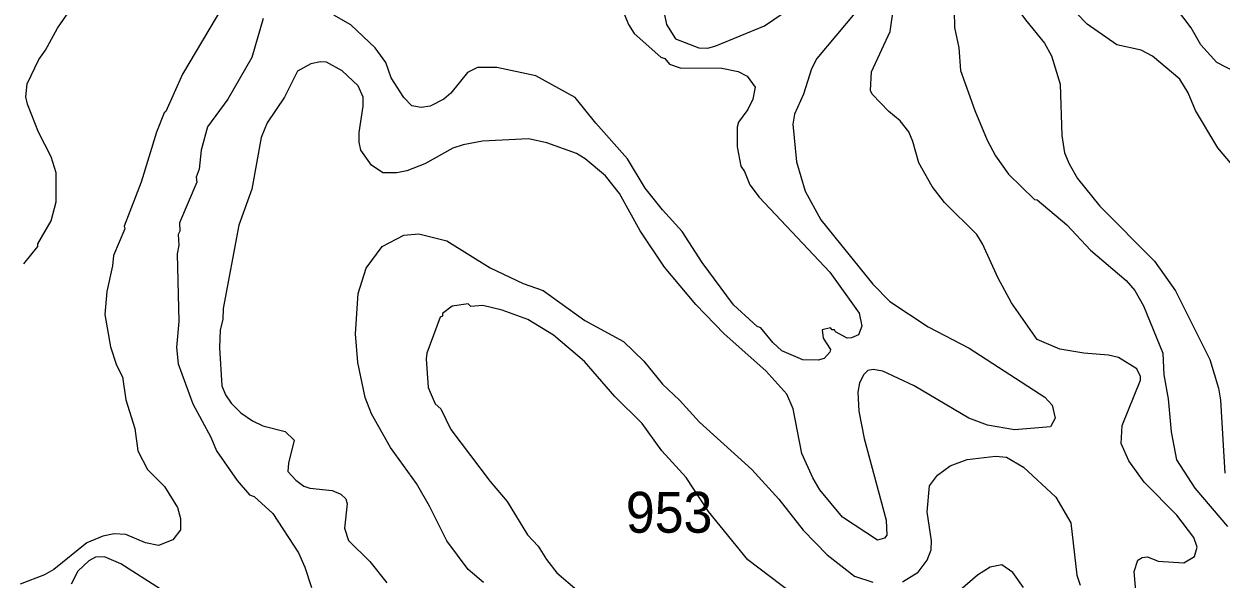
# Model space of a CAD drawing. Extents: x 447.8 to 473.9, y 7733.1 to 7760.8.
# Drawn here: x 451.054 to 453.399, y 7747.855 to 7748.942 of the extents above; entities that cross this region are included whole.
import ezdxf

# ---------------------------------------------------------------- set-up
doc = ezdxf.new("R2010")
doc.units = 0
doc.header["$LTSCALE"] = 0.032
doc.layers.add('1', color=7, linetype='Continuous', lineweight=25)
doc.layers.add('2', color=7, linetype='Continuous', lineweight=13)
doc.layers.add('21', color=7, linetype='Continuous')

msp = doc.modelspace()

# ---------------------------------------------------------------- linework, layer by layer
at = {"layer": '1'}
for points in [[(452.3083, 7748.9635), (452.3123, 7748.941), (452.3305, 7748.9134), (452.3757, 7748.8958), (452.3933, 7748.895), (452.4095, 7748.8993), (452.5046, 7748.9386), (452.5775, 7748.9883)], [(452.6817, 7748.9633), (452.6069, 7748.8749), (452.5964, 7748.8544), (452.5806, 7748.8048), (452.5632, 7748.7655), (452.56, 7748.7464), (452.5673, 7748.6725), (452.5842, 7748.6148), (452.6151, 7748.5585), (452.7169, 7748.4327), (452.7503, 7748.3985), (452.825, 7748.3492), (452.9055, 7748.3077), (453.0538, 7748.2111), (453.0681, 7748.1958), (453.0738, 7748.1705), (453.0648, 7748.1536), (452.9942, 7748.1471), (452.9413, 7748.1567), (452.905, 7748.1701), (452.7978, 7748.2338), (452.736, 7748.2625), (452.7172, 7748.2656), (452.7068, 7748.2639), (452.6988, 7748.256), (452.6906, 7748.2397), (452.6875, 7748.2212), (452.689, 7748.1843), (452.6997, 7748.1303), (452.7427, 7747.9707), (452.7442, 7747.9408), (452.7393, 7747.935), (452.7261, 7747.9311), (452.6574, 7747.9761), (452.6132, 7748.0297), (452.5989, 7748.0531), (452.5774, 7748.1013), (452.5609, 7748.1884), (452.5481, 7748.217), (452.5072, 7748.2631), (452.4253, 7748.3354), (452.3698, 7748.3926), (452.3089, 7748.4663), (452.2608, 7748.5369), (452.2208, 7748.6101), (452.193, 7748.6447), (452.1535, 7748.6779), (452.136, 7748.6889), (452.0782, 7748.7095), (452.0426, 7748.7177), (451.9524, 7748.7129), (451.9143, 7748.7058), (451.8944, 7748.6992), (451.8395, 7748.6685), (451.8041, 7748.6547), (451.7845, 7748.6505), (451.7572, 7748.6505), (451.7346, 7748.6656), (451.714, 7748.6951), (451.7104, 7748.711), (451.7104, 7748.7298), (451.7183, 7748.7816), (451.7183, 7748.7992), (451.7087, 7748.8214), (451.6776, 7748.8505), (451.6469, 7748.8673), (451.6346, 7748.8684), (451.6158, 7748.8644), (451.5902, 7748.8499), (451.5647, 7748.7988)], [(451.5647, 7748.7988), (451.5307, 7748.7487), (451.5186, 7748.7198), (451.5004, 7748.6187), (451.4747, 7748.5482), (451.4446, 7748.3853)], [(451.4446, 7748.3853), (451.4434, 7748.3634), (451.4386, 7748.3434), (451.4371, 7748.3083), (451.4419, 7748.2336), (451.4489, 7748.2163), (451.4601, 7748.1996), (451.479, 7748.1804), (451.5019, 7748.165), (451.522, 7748.1554), (451.5657, 7748.1439), (451.5834, 7748.127), (451.5721, 7748.0821), (451.5709, 7748.0656), (451.5867, 7748.0487), (451.6022, 7748.0373), (451.6142, 7748.0334), (451.6578, 7748.0283), (451.675, 7748.0211), (451.6846, 7748.0121), (451.687, 7748.0023), (451.6816, 7747.9551), (451.6896, 7747.9307), (451.7314, 7747.8895), (451.7651, 7747.848)]]:
    msp.add_lwpolyline(points, dxfattribs=at)
at = {"layer": '2'}
for points in [[(453.4872, 7748.5874), (453.3925, 7748.6995), (453.3485, 7748.7728), (453.3342, 7748.8078), (453.3181, 7748.8342), (453.2643, 7748.8795), (453.2423, 7748.8911), (453.1947, 7748.9015), (453.1364, 7748.9418), (453.1153, 7748.9633), (453.0416, 7749.0649), (452.9876, 7749.1081), (452.9487, 7749.1264), (452.9395, 7749.1254), (452.9296, 7749.1185), (452.9208, 7749.1038), (452.9208, 7749.0866), (452.9245, 7749.0742), (453.0157, 7748.9502), (453.0527, 7748.9048), (453.0665, 7748.88)], [(451.4433, 7748.9757), (451.3646, 7748.8439), (451.3321, 7748.7709), (451.3285, 7748.7682), (451.3135, 7748.7303), (451.2838, 7748.6326), (451.2504, 7748.5462), (451.2516, 7748.5412), (451.2296, 7748.4892), (451.2277, 7748.4689), (451.2163, 7748.4184), (451.2126, 7748.3736), (451.2238, 7748.3099), (451.2357, 7748.274), (451.247, 7748.2512), (451.2535, 7748.206), (451.2711, 7748.1502), (451.2773, 7748.106), (451.2963, 7748.0696), (451.3294, 7748.0367), (451.3548, 7747.9952), (451.3608, 7747.9739), (451.3608, 7747.9518), (451.3459, 7747.9317), (451.3177, 7747.9211), (451.2919, 7747.9258), (451.2534, 7747.9426), (451.231, 7747.9434), (451.2085, 7747.9394), (451.1776, 7747.9263), (451.1129, 7747.8741), (451.0944, 7747.8631), (451.0469, 7747.8449)], [(451.054, 7748.4728), (451.0816, 7748.5067), (451.0813, 7748.5118), (451.1073, 7748.557), (451.1171, 7748.5943), (451.117, 7748.6511), (451.1074, 7748.682), (451.0829, 7748.7304), (451.061, 7748.7854), (451.0578, 7748.7996), (451.0602, 7748.8248), (451.0834, 7748.873), (451.0964, 7748.8912), (451.12, 7748.9344), (451.1479, 7748.9748)], [(452.2189, 7748.9878), (452.2383, 7748.9412), (452.2491, 7748.9236), (452.3015, 7748.8773), (452.309, 7748.8747), (452.3185, 7748.8637), (452.3394, 7748.8565), (452.4208, 7748.8556), (452.4529, 7748.8491), (452.4704, 7748.84), (452.4862, 7748.8184), (452.4815, 7748.795), (452.4719, 7748.7747), (452.4535, 7748.7498), (452.4511, 7748.7405), (452.4511, 7748.7015), (452.458, 7748.6639), (452.4654, 7748.6536), (452.4758, 7748.6276), (452.494, 7748.6034), (452.6323, 7748.4562), (452.6897, 7748.3759), (452.6954, 7748.3506), (452.6884, 7748.3335), (452.6751, 7748.3274), (452.6665, 7748.3269), (452.6437, 7748.3395), (452.6419, 7748.3431), (452.6369, 7748.343), (452.6336, 7748.3473), (452.6174, 7748.3436), (452.6193, 7748.3269), (452.6336, 7748.3049), (452.6326, 7748.2997), (452.6214, 7748.287), (452.6097, 7748.2842), (452.5796, 7748.2846), (452.5383, 7748.3024), (452.5211, 7748.3182), (452.4975, 7748.3473), (452.4899, 7748.35), (452.4441, 7748.3921), (452.3824, 7748.4752), (452.3434, 7748.5361), (452.3046, 7748.5781), (452.271, 7748.621), (452.2359, 7748.678), (452.174, 7748.7479), (452.1338, 7748.7983), (452.0569, 7748.8411), (451.98, 7748.8572), (451.9424, 7748.8572), (451.9228, 7748.8476), (451.8901, 7748.8067), (451.8766, 7748.7952), (451.8495, 7748.7812), (451.8319, 7748.7787), (451.814, 7748.7817), (451.7981, 7748.7985), (451.7734, 7748.8371), (451.763, 7748.8671), (451.7422, 7748.8954), (451.6946, 7748.9404), (451.6613, 7748.9596)], [(453.2325, 7747.824), (453.2286, 7747.87), (453.2358, 7747.8924), (453.2444, 7747.8974), (453.2549, 7747.8984), (453.2758, 7747.8904), (453.3257, 7747.8868), (453.3468, 7747.8995), (453.3517, 7747.9179), (453.3453, 7747.9365), (453.3119, 7747.9802), (453.2481, 7748.0446), (453.2179, 7748.0867), (453.2033, 7748.1204), (453.2049, 7748.156), (453.2412, 7748.245), (453.2409, 7748.2519), (453.2335, 7748.2666), (453.1976, 7748.2889), (453.1781, 7748.2937), (453.1299, 7748.2978), (453.0827, 7748.3057), (453.0388, 7748.3243), (452.9881, 7748.3959), (452.9619, 7748.4446), (452.9314, 7748.5116), (452.9201, 7748.5297), (452.857, 7748.5927), (452.8326, 7748.624), (452.8065, 7748.6702), (452.7953, 7748.7123), (452.7869, 7748.7314), (452.7699, 7748.7529), (452.7479, 7748.771), (452.7157, 7748.805), (452.7124, 7748.8122), (452.7139, 7748.8487), (452.7506, 7748.9274), (452.7587, 7748.9816)], [(453.5469, 7748.7861), (453.3904, 7748.8669), (453.3588, 7748.9016), (453.3399, 7748.935), (453.2971, 7748.9922)], [(451.5225, 7748.9528), (451.5003, 7748.8765), (451.4534, 7748.7954), (451.4134, 7748.7407), (451.4014, 7748.6949), (451.3976, 7748.6577), (451.3914, 7748.642), (451.3929, 7748.6328), (451.3586, 7748.5529), (451.3592, 7748.5364), (451.3561, 7748.53), (451.3576, 7748.5093), (451.3545, 7748.4924), (451.3577, 7748.3596), (451.3528, 7748.3085)], [(452.8758, 7748.9678), (452.8767, 7748.9352), (452.8854, 7748.8957), (452.8887, 7748.8512), (452.9162, 7748.7732), (452.9405, 7748.715), (452.957, 7748.6842), (452.9824, 7748.6479), (453.0335, 7748.5987), (453.0387, 7748.5979), (453.0969, 7748.5487), (453.1433, 7748.4992), (453.2127, 7748.4402), (453.2297, 7748.4201), (453.2465, 7748.3901), (453.2846, 7748.2977), (453.2863, 7748.2554), (453.295, 7748.2079), (453.3008, 7748.1438), (453.3116, 7748.0887), (453.3472, 7748.0332), (453.4114, 7747.9584)], [(453.0665, 7748.88), (453.0833, 7748.8242), (453.0867, 7748.7238), (453.0923, 7748.6902), (453.101, 7748.6683), (453.1175, 7748.6398)], [(453.1175, 7748.6398), (453.1613, 7748.5855), (453.2686, 7748.4781), (453.3095, 7748.4195), (453.3767, 7748.2852), (453.3936, 7748.2288), (453.3977, 7748.2056), (453.4062, 7748.0623)], [(451.9542, 7747.8482), (451.9239, 7747.8741), (451.8821, 7747.9303), (451.8487, 7747.9982), (451.8228, 7748.0422), (451.7719, 7748.1131), (451.7346, 7748.1787), (451.7222, 7748.2106), (451.708, 7748.2793), (451.7032, 7748.3355), (451.7087, 7748.4146), (451.7246, 7748.4639), (451.7554, 7748.5067), (451.7984, 7748.5284), (451.8274, 7748.5316), (451.8821, 7748.5179), (451.967, 7748.465), (452.0321, 7748.4342), (452.0709, 7748.4202), (452.1529, 7748.3614), (452.2283, 7748.3206), (452.2685, 7748.282), (452.3048, 7748.2371), (452.3378, 7748.2056), (452.3772, 7748.1622)], [(452.5797, 7747.8113), (452.4721, 7747.8927), (452.395, 7747.9875), (452.3512, 7748.0538), (452.3035, 7748.1063), (452.2648, 7748.1601), (452.2113, 7748.2128), (452.1518, 7748.2812), (452.0913, 7748.3327), (452.0409, 7748.3633), (451.9905, 7748.3816), (451.9527, 7748.3912), (451.9296, 7748.3892), (451.9239, 7748.3939), (451.8925, 7748.3898), (451.8741, 7748.3754), (451.8736, 7748.3699), (451.8693, 7748.3681), (451.8434, 7748.2973), (451.8419, 7748.2862), (451.8459, 7748.2301)], [(451.3528, 7748.3085), (451.3561, 7748.2766), (451.3851, 7748.1981), (451.42, 7748.1329), (451.4311, 7748.1062), (451.4714, 7748.0482)], [(451.8459, 7748.2301), (451.8596, 7748.1985), (451.8706, 7748.1887), (451.8901, 7748.1484), (451.9673, 7748.046), (452.0007, 7748.0073)], [(452.3772, 7748.1622), (452.4794, 7748.0695), (452.5326, 7748.0114), (452.5802, 7747.9511), (452.6273, 7747.9024), (452.6807, 7747.8605)], [(452.7751, 7747.85), (452.8056, 7747.8688), (452.8228, 7747.8921), (452.8309, 7747.9123), (452.8316, 7747.9298), (452.823, 7747.9867), (452.8279, 7748.0379), (452.8434, 7748.0584), (452.868, 7748.0771), (452.9015, 7748.0892), (452.9571, 7748.0956), (452.9785, 7748.0937), (453.0119, 7748.0744), (453.0751, 7748.0157), (453.1048, 7747.9653), (453.1163, 7747.863), (453.1227, 7747.8435)], [(451.4714, 7748.0482), (451.4961, 7748.0201), (451.5051, 7748.0169), (451.5414, 7747.9833), (451.5918, 7747.9062), (451.6043, 7747.8784), (451.6171, 7747.8383)], [(452.0007, 7748.0073), (452.0405, 7747.942), (452.0613, 7747.9194), (452.0773, 7747.8932), (452.0981, 7747.8676), (452.1379, 7747.8332)], [(451.3214, 7747.8356), (451.2436, 7747.8851), (451.2122, 7747.8985), (451.194, 7747.8978), (451.1811, 7747.8907), (451.1595, 7747.8707), (451.1464, 7747.8451)], [(453.0116, 7747.8386), (452.9908, 7747.8678), (452.9693, 7747.8833), (452.9464, 7747.8784), (452.922, 7747.8628), (452.8876, 7747.8334)], [(452.6807, 7747.8605), (452.7168, 7747.8489)]]:
    msp.add_lwpolyline(points, dxfattribs=at)

# ---------------------------------------------------------------- texts
at = {"layer": '21', "width": 0.95}
msp.add_text('953', height=0.08, dxfattribs=at).set_placement((452.2329, 7747.9459))

doc.saveas('drawing.dxf')
